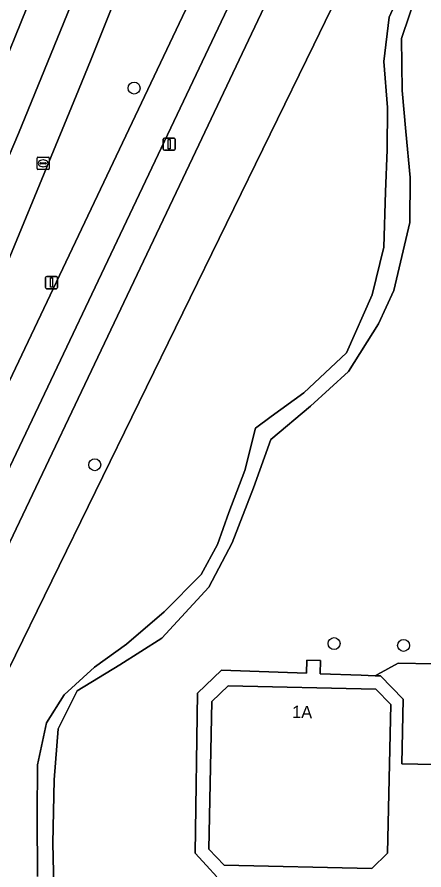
# Model space of a CAD drawing. Extents: x 161477 to 163040, y 383680 to 384871.
# Drawn here: x 161758.7 to 161791.9, y 384680.7 to 384750.3 of the extents above; entities that cross this region are included whole.
import ezdxf

# ---------------------------------------------------------------- set-up
doc = ezdxf.new("R2010")
doc.units = 0
for name, color, linetype in [('IMGEO_Berm_groen', 7, 'Continuous'), ('IMGEO_Boom', 7, 'Continuous'), ('IMGEO_Fietspad_gesloten', 7, 'Continuous'), ('IMGEO_Groenvoorziening', 7, 'Continuous'), ('IMGEO_Hek', 7, 'Continuous'), ('IMGEO_Kolk', 7, 'Continuous'), ('IMGEO_Lichtmast', 7, 'Continuous'), ('IMGEO_Pand', 7, 'Continuous'), ('IMGEO_Pand_nummerreeks', 7, 'Continuous'), ('IMGEO_Rijbaan_lokaal_gesloten', 7, 'Continuous'), ('IMGEO_Voetpad_onverhard', 7, 'Continuous'), ('IMGEO_Voetpad_open', 7, 'Continuous')]:
    doc.layers.add(name, color=color, linetype=linetype)

msp = doc.modelspace()

# ---------------------------------------------------------------- linework, layer by layer
at = {"layer": 'IMGEO_Berm_groen'}
msp.add_lwpolyline([(161769.245, 384758.083), (161764.688, 384746.722), (161763.528, 384743.867), (161755.837, 384725.304), (161751.324, 384714.413), (161754.426, 384712.973), (161799.435, 384807.726), (161800.209, 384809.412), (161800.411, 384809.395)], dxfattribs=at)
at = {"layer": 'IMGEO_Boom'}
for centre in [(161768.254, 384744.495), (161765.04, 384713.757), (161784.57, 384699.15), (161790.25, 384699.01)]:
    msp.add_circle(centre, 0.489, dxfattribs=at)
at = {"layer": 'IMGEO_Fietspad_gesloten'}
msp.add_lwpolyline([(161799.435, 384807.726), (161754.426, 384712.973), (161751.189, 384706.159), (161749.453, 384702.505), (161746.32, 384695.97), (161745.018, 384693.255), (161744.965, 384693.145), (161739.384, 384681.875), (161711.461, 384625.223), (161700.139, 384602.578), (161690.92, 384583.94), (161691.015, 384583.889), (161690.919, 384583.725), (161693.509, 384582.44), (161700.887, 384597.12), (161714.176, 384623.884), (161742.249, 384680.698), (161742.516, 384681.245), (161744.067, 384684.424), (161747.376, 384691.207), (161750.618, 384697.888), (161803.161, 384808.473)], dxfattribs=at)
at = {"layer": 'IMGEO_Groenvoorziening'}
for points in [[(161804.698, 384805.476), (161800.478, 384796.565), (161778.347, 384750), (161773.012, 384738.776), (161751.678, 384693.98), (161741.125, 384672.506), (161729.219, 384648.412), (161733.008, 384645.95), (161782.919, 384748.037), (161810.108, 384804.005), (161836.574, 384803.916), (161949.969, 384804.107), (162038.287, 384809.499)], [(161949.969, 384804.107), (161836.574, 384803.916), (161810.108, 384804.005), (161782.919, 384748.037), (161733.008, 384645.95), (161725.311, 384630.208), (161692.773, 384563.441)], [(161775.011, 384680.111), (161774.153, 384681.043), (161773.232, 384682.043), (161773.413, 384695.109), (161775.382, 384696.989), (161782.317, 384696.738), (161782.356, 384697.808), (161783.475, 384697.767), (161783.437, 384696.698), (161786.795, 384696.577), (161787.931, 384696.536), (161788.112, 384696.635), (161789.812, 384697.566), (161801.237, 384697.353), (161802.445, 384750), (161802.939, 384771.548)], [(161760.378, 384680.158), (161760.346, 384685.127), (161760.362, 384689.254), (161761.096, 384692.69), (161762.55, 384694.973), (161765.018, 384697.222), (161767.627, 384699.098), (161770.706, 384701.754), (161773.738, 384704.786), (161775.066, 384707.255), (161775.971, 384709.85), (161777.283, 384713.287), (161778.158, 384716.726), (161779.439, 384717.694), (161782.111, 384719.633), (161785.58, 384722.882), (161787.69, 384727.633), (161788.627, 384731.509), (161788.783, 384736.041), (161788.908, 384739.446), (161788.923, 384742.915), (161788.642, 384746.666), (161789.079, 384750.291), (161790.19, 384752.761)], [(161791.407, 384752.51), (161790.079, 384748.541), (161790.142, 384744.29), (161790.439, 384740.946), (161790.783, 384737.197), (161790.744, 384733.513), (161789.458, 384727.983), (161788.19, 384725.257), (161785.752, 384721.351), (161782.643, 384718.538), (161779.424, 384715.819), (161778.002, 384711.881), (161776.268, 384707.381), (161774.362, 384703.755), (161770.518, 384699.598), (161767.082, 384697.41), (161763.612, 384695.286), (161762.05, 384692.19), (161761.738, 384688.034), (161761.628, 384682.878), (161761.738, 384678.127)]]:
    msp.add_lwpolyline(points, dxfattribs=at)
at = {"layer": 'IMGEO_Hek'}
for points in [[(162038.287, 384809.499), (161949.969, 384804.107), (161836.574, 384803.916), (161810.108, 384804.005), (161782.919, 384748.037)], [(161782.919, 384748.037), (161733.008, 384645.95)]]:
    msp.add_lwpolyline(points, dxfattribs=at)
at = {"layer": 'IMGEO_Kolk'}
for p, q in [((161760.329, 384737.929), (161760.329, 384738.781)), ((161760.404, 384738.855), (161761.256, 384738.855)), ((161760.817, 384738.635), (161760.842, 384738.635)), ((161761.33, 384738.781), (161761.33, 384737.929)), ((161760.588, 384738.349), (161760.588, 384738.361)), ((161761.026, 384738.312), (161760.628, 384738.312)), ((161760.631, 384738.398), (161761.029, 384738.398)), ((161760.84, 384738.075), (161760.815, 384738.075)), ((161761.072, 384738.361), (161761.072, 384738.349)), ((161761.256, 384737.855), (161760.404, 384737.855))]:
    msp.add_line(p, q, dxfattribs=at)
for points in [[(161760.329, 384737.929), (161760.329, 384738.781)], [(161760.404, 384738.855), (161761.256, 384738.855)], [(161761.33, 384738.781), (161761.33, 384737.929)], [(161761.256, 384737.855), (161760.404, 384737.855)]]:
    msp.add_lwpolyline(points, dxfattribs=at)
for centre, radius, start, end in [((161760.406, 384738.779), 0.0765, 91.55205, 178.44795), ((161760.406, 384738.779), 0.0765, 91.55205, 178.44795), ((161761.254, 384738.779), 0.0765, 1.55205, 88.44795), ((161761.254, 384738.779), 0.0765, 1.55205, 88.44795), ((161760.406, 384737.931), 0.0765, 181.55205, 268.44795), ((161760.406, 384737.931), 0.0765, 181.55205, 268.44795), ((161760.628, 384738.358), 0.0403, 85.87752, 175.75265), ((161760.625, 384738.348), 0.0366, 178.93798, 274.71019), ((161761.029, 384738.355), 0.043, 264.86636, 352.45326), ((161761.033, 384738.36), 0.0386, 1.73085, 96.63898), ((161761.254, 384737.931), 0.0765, 271.55205, 358.44795), ((161761.254, 384737.931), 0.0765, 271.55205, 358.44795)]:
    msp.add_arc(centre, radius, start, end, dxfattribs=at)
for centre, major_axis, ratio, start_param, end_param in [((161760.816, 384738.355), (-0.387, 0.002), 0.722429, 4.712389, 7.853982), ((161760.841, 384738.355), (-0.39, 0.002), 0.717154, 1.570796, 4.712389)]:
    msp.add_ellipse(centre, major_axis=major_axis, ratio=ratio, start_param=start_param, end_param=end_param, dxfattribs=at)
at = {"layer": 'IMGEO_Lichtmast'}
for p, q in [((161770.623, 384739.518), (161770.623, 384740.318)), ((161770.623, 384740.318), (161770.623, 384739.518)), ((161770.723, 384740.418), (161771.513, 384740.418)), ((161771.513, 384740.418), (161770.723, 384740.418)), ((161771.613, 384740.318), (161771.613, 384739.518)), ((161771.613, 384739.518), (161771.613, 384740.318)), ((161771.513, 384739.418), (161770.723, 384739.418)), ((161770.723, 384739.418), (161771.513, 384739.418)), ((161761.017, 384728.222), (161761.017, 384729.022)), ((161761.017, 384729.022), (161761.017, 384728.222)), ((161761.117, 384729.122), (161761.907, 384729.122)), ((161761.907, 384729.122), (161761.117, 384729.122)), ((161762.007, 384729.022), (161762.007, 384728.222)), ((161762.007, 384728.222), (161762.007, 384729.022)), ((161761.907, 384728.122), (161761.117, 384728.122)), ((161761.117, 384728.122), (161761.907, 384728.122))]:
    msp.add_line(p, q, dxfattribs=at)
for points in [[(161771.043, 384740.293), (161771.193, 384740.293), (161771.193, 384739.543), (161771.043, 384739.543), (161771.043, 384740.293)], [(161761.437, 384728.997), (161761.587, 384728.997), (161761.587, 384728.247), (161761.437, 384728.247), (161761.437, 384728.997)]]:
    msp.add_lwpolyline(points, dxfattribs=at)
for centre, start, end in [((161770.723, 384740.318), 90, 180), ((161770.723, 384740.318), 90, 180), ((161771.513, 384740.318), 0, 90), ((161771.513, 384740.318), 360, 90), ((161770.723, 384739.518), 180, 270), ((161770.723, 384739.518), 180, 270), ((161771.513, 384739.518), 270, 0), ((161771.513, 384739.518), 270, 0), ((161761.117, 384729.022), 90, 180), ((161761.117, 384729.022), 90, 180), ((161761.907, 384729.022), 0, 90), ((161761.907, 384729.022), 360, 90), ((161761.117, 384728.222), 180, 270), ((161761.117, 384728.222), 180, 270), ((161761.907, 384728.222), 270, 0), ((161761.907, 384728.222), 270, 0)]:
    msp.add_arc(centre, 0.1, start, end, dxfattribs=at)
at = {"layer": 'IMGEO_Pand'}
msp.add_lwpolyline([(161789.202, 384694.179), (161787.985, 384695.448), (161775.926, 384695.705), (161774.6, 384694.435), (161774.343, 384682.382), (161775.609, 384681.061), (161787.653, 384680.804), (161788.943, 384682.04)], close=True, dxfattribs=at)
at = {"layer": 'IMGEO_Rijbaan_lokaal_gesloten'}
for points in [[(161776.651, 384777.152), (161779.911, 384785.807), (161783.746, 384796.333), (161788.981, 384810.894), (161785.713, 384811.289), (161784.924, 384809.201), (161780.766, 384797.546), (161777.922, 384789.728), (161773.939, 384779.135), (161770.612, 384770.45), (161766.507, 384759.932), (161763.84, 384753.151), (161758.808, 384740.796), (161752.761, 384726.567), (161753.243, 384726.355), (161755.837, 384725.304), (161763.528, 384743.867), (161764.688, 384746.722), (161769.245, 384758.083)], [(161760.835, 384754.354), (161755.815, 384742.028), (161748.309, 384723.999), (161743.878, 384713.755), (161743.877, 384713.753), (161739.051, 384702.742), (161734.13, 384691.774), (161729.114, 384680.849), (161724.045, 384669.988), (161718.874, 384659.176), (161713.602, 384648.412), (161713.599, 384648.405), (161707.595, 384636.365), (161703.098, 384627.451), (161683.226, 384588.391), (161685.811, 384586.321), (161686.139, 384586.943), (161686.904, 384588.44), (161696.285, 384606.969), (161703.308, 384620.714), (161710.728, 384635.382)], [(161707.595, 384636.365), (161713.599, 384648.405), (161713.602, 384648.412), (161718.874, 384659.176), (161724.045, 384669.988), (161729.114, 384680.849), (161734.13, 384691.774), (161739.051, 384702.742), (161743.877, 384713.753), (161743.878, 384713.755), (161748.309, 384723.999), (161755.815, 384742.028), (161760.835, 384754.354)], [(161752.761, 384726.567), (161758.808, 384740.796), (161763.84, 384753.151)]]:
    msp.add_lwpolyline(points, dxfattribs=at)
at = {"layer": 'IMGEO_Voetpad_onverhard'}
for points in [[(161790.19, 384752.761), (161789.079, 384750.291), (161788.642, 384746.666), (161788.923, 384742.915), (161788.908, 384739.446), (161788.783, 384736.041), (161788.627, 384731.509), (161787.69, 384727.633), (161785.58, 384722.882), (161782.111, 384719.633), (161779.439, 384717.694), (161778.158, 384716.726), (161777.283, 384713.287), (161775.971, 384709.85), (161775.066, 384707.255), (161773.738, 384704.786), (161770.706, 384701.754), (161767.627, 384699.098), (161765.018, 384697.222), (161762.55, 384694.973), (161761.096, 384692.69), (161760.362, 384689.254), (161760.346, 384685.127), (161760.378, 384680.158)], [(161761.738, 384678.127), (161761.628, 384682.878), (161761.738, 384688.034), (161762.05, 384692.19), (161763.612, 384695.286), (161767.082, 384697.41), (161770.518, 384699.598), (161774.362, 384703.755), (161776.268, 384707.381), (161778.002, 384711.881), (161779.424, 384715.819), (161782.643, 384718.538), (161785.752, 384721.351), (161788.19, 384725.257), (161789.458, 384727.983), (161790.744, 384733.513), (161790.783, 384737.197), (161790.439, 384740.946), (161790.142, 384744.29), (161790.079, 384748.541), (161791.407, 384752.51)]]:
    msp.add_lwpolyline(points, dxfattribs=at)
at = {"layer": 'IMGEO_Voetpad_open'}
for points in [[(161803.913, 384809.963), (161803.161, 384808.473), (161750.618, 384697.888), (161747.376, 384691.207), (161744.067, 384684.424), (161742.516, 384681.245), (161742.249, 384680.698), (161714.176, 384623.884), (161700.887, 384597.12), (161693.509, 384582.44), (161686.205, 384568.22)], [(161751.678, 384693.98), (161773.012, 384738.776), (161778.347, 384750), (161800.478, 384796.565), (161804.698, 384805.476)], [(161802.939, 384771.548), (161802.445, 384750), (161801.237, 384697.353), (161789.812, 384697.566), (161788.112, 384696.635), (161787.931, 384696.536), (161788.361, 384696.52), (161790.202, 384694.627), (161790.117, 384689.349), (161795.312, 384689.228), (161797.2, 384687.169), (161797.118, 384683.925), (161811.199, 384683.662), (161811.208, 384684.11), (161811.492, 384698.994), (161805.791, 384699.101), (161805.808, 384699.651), (161806.36, 384717.02), (161806.653, 384717.024), (161807.448, 384750), (161807.482, 384751.399)], [(161850.611, 384682.926), (161811.199, 384683.662), (161797.118, 384683.925), (161797.2, 384687.169), (161795.312, 384689.228), (161790.117, 384689.349), (161790.202, 384694.627), (161788.361, 384696.52), (161787.931, 384696.536), (161786.795, 384696.577), (161783.437, 384696.698), (161783.475, 384697.767), (161782.356, 384697.808), (161782.317, 384696.738), (161775.382, 384696.989), (161773.413, 384695.109), (161773.232, 384682.043), (161774.153, 384681.043), (161775.011, 384680.111)]]:
    msp.add_lwpolyline(points, dxfattribs=at)
msp.add_lwpolyline([(161787.653, 384680.804), (161775.609, 384681.061), (161774.343, 384682.382), (161774.6, 384694.435), (161775.926, 384695.705), (161787.985, 384695.448), (161789.202, 384694.179), (161788.943, 384682.04)], close=True, dxfattribs=at)

# ---------------------------------------------------------------- texts
at = {"layer": 'IMGEO_Pand_nummerreeks'}
msp.add_text('1A', height=1, rotation=358.7796, dxfattribs=at).set_placement((161781.142, 384693.093))

doc.saveas('drawing.dxf')
